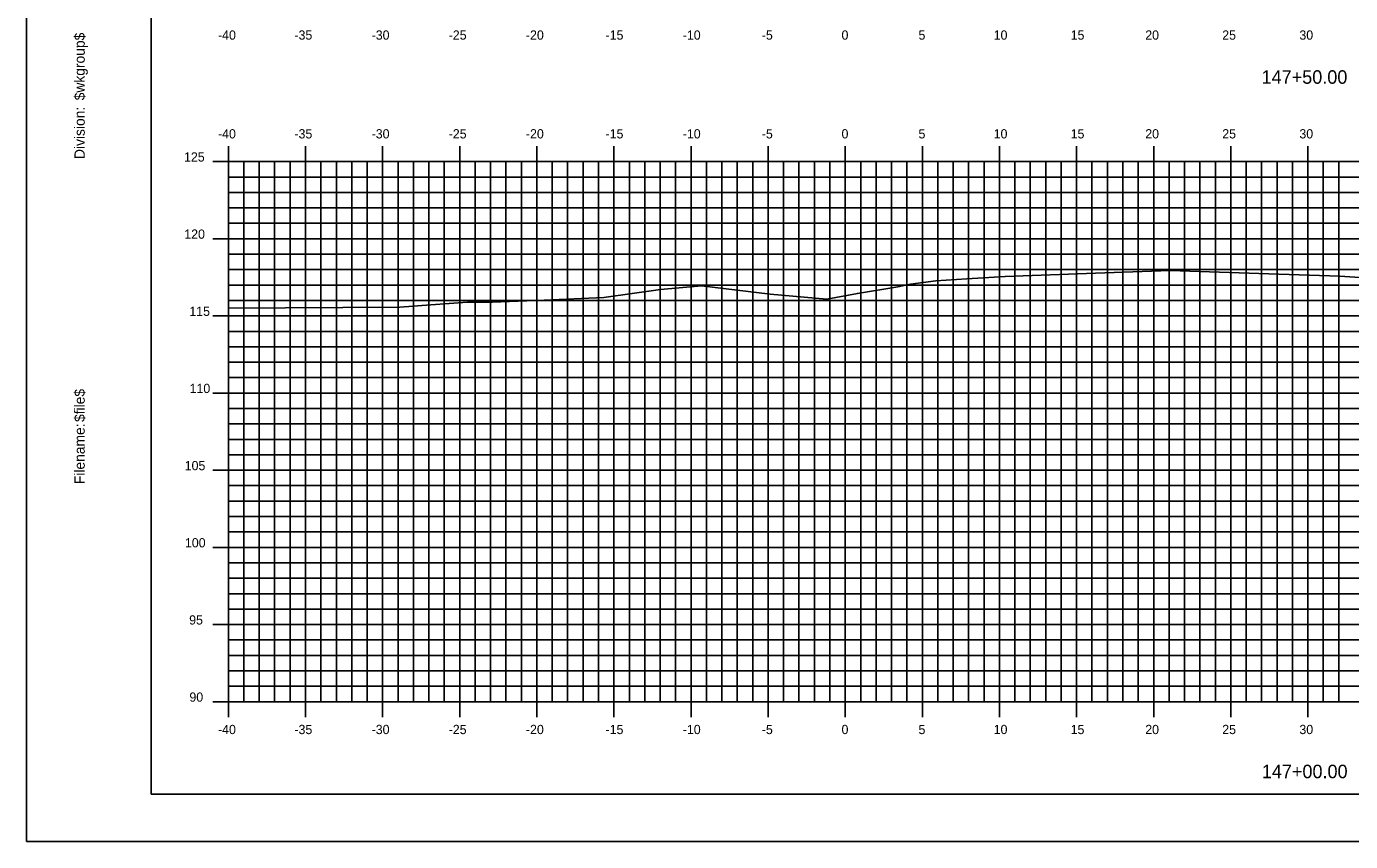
# Model space of a CAD drawing. Extents: x 850598 to 870284, y 366541 to 366651.
# Drawn here: x 850597.8 to 850683.7, y 366541.2 to 366594 of the extents above; entities that cross this region are included whole.
import ezdxf

# ---------------------------------------------------------------- set-up
doc = ezdxf.new("R2010")
doc.units = 0
for name, color, linetype in [('BORDER', 7, 'Continuous'), ('H_V ANNOTATION', 7, 'Continuous'), ('MAJOR', 7, 'Continuous'), ('MINOR', 7, 'Continuous'), ('PLOT BOUNDARY', 7, 'Continuous'), ('S_Roadway_Centerline', 7, 'Continuous')]:
    doc.layers.add(name, color=color, linetype=linetype)

msp = doc.modelspace()

# ---------------------------------------------------------------- linework, layer by layer
at = {"layer": 'BORDER'}
for p, q in [((850605.897, 366649.225), (850605.897, 366544.225)), ((850605.897, 366544.225), (850765.897, 366544.225))]:
    msp.add_line(p, q, dxfattribs=at)
at = {"layer": 'MAJOR'}
for p, q in [((850610.897, 366586.227), (850610.897, 366585.225)), ((850610.897, 366586.227), (850610.897, 366585.225)), ((850615.897, 366586.227), (850615.897, 366585.225)), ((850615.897, 366586.227), (850615.897, 366585.225)), ((850620.897, 366586.227), (850620.897, 366585.225)), ((850620.897, 366586.227), (850620.897, 366585.225)), ((850625.897, 366586.227), (850625.897, 366585.225)), ((850625.897, 366586.227), (850625.897, 366585.225)), ((850630.897, 366586.227), (850630.897, 366585.225)), ((850630.897, 366586.227), (850630.897, 366585.225)), ((850635.897, 366586.227), (850635.897, 366585.225)), ((850635.897, 366586.227), (850635.897, 366585.225)), ((850640.897, 366586.227), (850640.897, 366585.225)), ((850640.897, 366586.227), (850640.897, 366585.225)), ((850645.897, 366586.227), (850645.897, 366585.225)), ((850645.897, 366586.227), (850645.897, 366585.225)), ((850650.897, 366586.227), (850650.897, 366585.225)), ((850650.897, 366586.227), (850650.897, 366585.225)), ((850655.897, 366586.227), (850655.897, 366585.225)), ((850655.897, 366586.227), (850655.897, 366585.225)), ((850660.897, 366586.227), (850660.897, 366585.225)), ((850660.897, 366586.227), (850660.897, 366585.225)), ((850665.897, 366586.227), (850665.897, 366585.225)), ((850665.897, 366586.227), (850665.897, 366585.225)), ((850670.897, 366586.227), (850670.897, 366585.225)), ((850670.897, 366586.227), (850670.897, 366585.225)), ((850675.897, 366586.227), (850675.897, 366585.225)), ((850675.897, 366586.227), (850675.897, 366585.225)), ((850680.897, 366586.227), (850680.897, 366585.225)), ((850680.897, 366586.227), (850680.897, 366585.225)), ((850609.895, 366585.225), (850610.897, 366585.225)), ((850609.895, 366585.225), (850610.897, 366585.225)), ((850610.897, 366585.225), (850750.897, 366585.225)), ((850610.897, 366550.225), (850610.897, 366585.225)), ((850610.897, 366550.225), (850610.897, 366585.225)), ((850610.897, 366585.225), (850750.897, 366585.225)), ((850610.897, 366585.225), (850750.897, 366585.225)), ((850610.897, 366550.225), (850610.897, 366585.225)), ((850610.897, 366550.225), (850610.897, 366585.225)), ((850610.897, 366585.225), (850750.897, 366585.225)), ((850615.897, 366550.225), (850615.897, 366585.225)), ((850615.897, 366550.225), (850615.897, 366585.225)), ((850620.897, 366550.225), (850620.897, 366585.225)), ((850620.897, 366550.225), (850620.897, 366585.225)), ((850625.897, 366550.225), (850625.897, 366585.225)), ((850625.897, 366550.225), (850625.897, 366585.225)), ((850630.897, 366550.225), (850630.897, 366585.225)), ((850630.897, 366550.225), (850630.897, 366585.225)), ((850635.897, 366550.225), (850635.897, 366585.225)), ((850635.897, 366550.225), (850635.897, 366585.225)), ((850640.897, 366550.225), (850640.897, 366585.225)), ((850640.897, 366550.225), (850640.897, 366585.225)), ((850645.897, 366550.225), (850645.897, 366585.225)), ((850645.897, 366550.225), (850645.897, 366585.225)), ((850650.897, 366550.225), (850650.897, 366585.225)), ((850650.897, 366550.225), (850650.897, 366585.225)), ((850655.897, 366550.225), (850655.897, 366585.225)), ((850655.897, 366550.225), (850655.897, 366585.225)), ((850660.897, 366550.225), (850660.897, 366585.225)), ((850660.897, 366550.225), (850660.897, 366585.225)), ((850665.897, 366550.225), (850665.897, 366585.225)), ((850665.897, 366550.225), (850665.897, 366585.225)), ((850670.897, 366550.225), (850670.897, 366585.225)), ((850670.897, 366550.225), (850670.897, 366585.225)), ((850675.897, 366550.225), (850675.897, 366585.225)), ((850675.897, 366550.225), (850675.897, 366585.225)), ((850680.897, 366550.225), (850680.897, 366585.225)), ((850680.897, 366550.225), (850680.897, 366585.225)), ((850609.895, 366580.225), (850610.897, 366580.225)), ((850609.895, 366580.225), (850610.897, 366580.225)), ((850610.897, 366580.225), (850750.897, 366580.225)), ((850610.897, 366580.225), (850750.897, 366580.225)), ((850609.895, 366575.225), (850610.897, 366575.225)), ((850609.895, 366575.225), (850610.897, 366575.225)), ((850610.897, 366575.225), (850750.897, 366575.225)), ((850610.897, 366575.225), (850750.897, 366575.225)), ((850609.895, 366570.225), (850610.897, 366570.225)), ((850609.895, 366570.225), (850610.897, 366570.225)), ((850610.897, 366570.225), (850750.897, 366570.225)), ((850610.897, 366570.225), (850750.897, 366570.225)), ((850609.895, 366565.225), (850610.897, 366565.225)), ((850609.895, 366565.225), (850610.897, 366565.225)), ((850610.897, 366565.225), (850750.897, 366565.225)), ((850610.897, 366565.225), (850750.897, 366565.225)), ((850609.895, 366560.225), (850610.897, 366560.225)), ((850609.895, 366560.225), (850610.897, 366560.225)), ((850610.897, 366560.225), (850750.897, 366560.225)), ((850610.897, 366560.225), (850750.897, 366560.225)), ((850609.895, 366555.225), (850610.897, 366555.225)), ((850609.895, 366555.225), (850610.897, 366555.225)), ((850610.897, 366555.225), (850750.897, 366555.225)), ((850610.897, 366555.225), (850750.897, 366555.225)), ((850609.895, 366550.225), (850610.897, 366550.225)), ((850609.895, 366550.225), (850610.897, 366550.225)), ((850610.897, 366550.225), (850750.897, 366550.225)), ((850610.897, 366550.225), (850750.897, 366550.225)), ((850610.897, 366549.223), (850610.897, 366550.225)), ((850610.897, 366550.225), (850750.897, 366550.225)), ((850610.897, 366550.225), (850750.897, 366550.225)), ((850610.897, 366549.223), (850610.897, 366550.225)), ((850615.897, 366549.223), (850615.897, 366550.225)), ((850615.897, 366549.223), (850615.897, 366550.225)), ((850620.897, 366549.223), (850620.897, 366550.225)), ((850620.897, 366549.223), (850620.897, 366550.225)), ((850625.897, 366549.223), (850625.897, 366550.225)), ((850625.897, 366549.223), (850625.897, 366550.225)), ((850630.897, 366549.223), (850630.897, 366550.225)), ((850630.897, 366549.223), (850630.897, 366550.225)), ((850635.897, 366549.223), (850635.897, 366550.225)), ((850635.897, 366549.223), (850635.897, 366550.225)), ((850640.897, 366549.223), (850640.897, 366550.225)), ((850640.897, 366549.223), (850640.897, 366550.225)), ((850645.897, 366549.223), (850645.897, 366550.225)), ((850645.897, 366549.223), (850645.897, 366550.225)), ((850650.897, 366549.223), (850650.897, 366550.225)), ((850650.897, 366549.223), (850650.897, 366550.225)), ((850655.897, 366549.223), (850655.897, 366550.225)), ((850655.897, 366549.223), (850655.897, 366550.225)), ((850660.897, 366549.223), (850660.897, 366550.225)), ((850660.897, 366549.223), (850660.897, 366550.225)), ((850665.897, 366549.223), (850665.897, 366550.225)), ((850665.897, 366549.223), (850665.897, 366550.225)), ((850670.897, 366549.223), (850670.897, 366550.225)), ((850670.897, 366549.223), (850670.897, 366550.225)), ((850675.897, 366549.223), (850675.897, 366550.225)), ((850675.897, 366549.223), (850675.897, 366550.225)), ((850680.897, 366549.223), (850680.897, 366550.225)), ((850680.897, 366549.223), (850680.897, 366550.225))]:
    msp.add_line(p, q, dxfattribs=at)
at = {"layer": 'MINOR'}
for p, q in [((850611.897, 366550.225), (850611.897, 366585.225)), ((850611.897, 366550.225), (850611.897, 366585.225)), ((850612.897, 366550.225), (850612.897, 366585.225)), ((850612.897, 366550.225), (850612.897, 366585.225)), ((850613.897, 366550.225), (850613.897, 366585.225)), ((850613.897, 366550.225), (850613.897, 366585.225)), ((850614.897, 366550.225), (850614.897, 366585.225)), ((850614.897, 366550.225), (850614.897, 366585.225)), ((850616.897, 366550.225), (850616.897, 366585.225)), ((850616.897, 366550.225), (850616.897, 366585.225)), ((850617.897, 366550.225), (850617.897, 366585.225)), ((850617.897, 366550.225), (850617.897, 366585.225)), ((850618.897, 366550.225), (850618.897, 366585.225)), ((850618.897, 366550.225), (850618.897, 366585.225)), ((850619.897, 366550.225), (850619.897, 366585.225)), ((850619.897, 366550.225), (850619.897, 366585.225)), ((850621.897, 366550.225), (850621.897, 366585.225)), ((850621.897, 366550.225), (850621.897, 366585.225)), ((850622.897, 366550.225), (850622.897, 366585.225)), ((850622.897, 366550.225), (850622.897, 366585.225)), ((850623.897, 366550.225), (850623.897, 366585.225)), ((850623.897, 366550.225), (850623.897, 366585.225)), ((850624.897, 366550.225), (850624.897, 366585.225)), ((850624.897, 366550.225), (850624.897, 366585.225)), ((850626.897, 366550.225), (850626.897, 366585.225)), ((850626.897, 366550.225), (850626.897, 366585.225)), ((850627.897, 366550.225), (850627.897, 366585.225)), ((850627.897, 366550.225), (850627.897, 366585.225)), ((850628.897, 366550.225), (850628.897, 366585.225)), ((850628.897, 366550.225), (850628.897, 366585.225)), ((850629.897, 366550.225), (850629.897, 366585.225)), ((850629.897, 366550.225), (850629.897, 366585.225)), ((850631.897, 366550.225), (850631.897, 366585.225)), ((850631.897, 366550.225), (850631.897, 366585.225)), ((850632.897, 366550.225), (850632.897, 366585.225)), ((850632.897, 366550.225), (850632.897, 366585.225)), ((850633.897, 366550.225), (850633.897, 366585.225)), ((850633.897, 366550.225), (850633.897, 366585.225)), ((850634.897, 366550.225), (850634.897, 366585.225)), ((850634.897, 366550.225), (850634.897, 366585.225)), ((850636.897, 366550.225), (850636.897, 366585.225)), ((850636.897, 366550.225), (850636.897, 366585.225)), ((850637.897, 366550.225), (850637.897, 366585.225)), ((850637.897, 366550.225), (850637.897, 366585.225)), ((850638.897, 366550.225), (850638.897, 366585.225)), ((850638.897, 366550.225), (850638.897, 366585.225)), ((850639.897, 366550.225), (850639.897, 366585.225)), ((850639.897, 366550.225), (850639.897, 366585.225)), ((850641.897, 366550.225), (850641.897, 366585.225)), ((850641.897, 366550.225), (850641.897, 366585.225)), ((850642.897, 366550.225), (850642.897, 366585.225)), ((850642.897, 366550.225), (850642.897, 366585.225)), ((850643.897, 366550.225), (850643.897, 366585.225)), ((850643.897, 366550.225), (850643.897, 366585.225)), ((850644.897, 366550.225), (850644.897, 366585.225)), ((850644.897, 366550.225), (850644.897, 366585.225)), ((850646.897, 366550.225), (850646.897, 366585.225)), ((850646.897, 366550.225), (850646.897, 366585.225)), ((850647.897, 366550.225), (850647.897, 366585.225)), ((850647.897, 366550.225), (850647.897, 366585.225)), ((850648.897, 366550.225), (850648.897, 366585.225)), ((850648.897, 366550.225), (850648.897, 366585.225)), ((850649.897, 366550.225), (850649.897, 366585.225)), ((850649.897, 366550.225), (850649.897, 366585.225)), ((850651.897, 366550.225), (850651.897, 366585.225)), ((850651.897, 366550.225), (850651.897, 366585.225)), ((850652.897, 366550.225), (850652.897, 366585.225)), ((850652.897, 366550.225), (850652.897, 366585.225)), ((850653.897, 366550.225), (850653.897, 366585.225)), ((850653.897, 366550.225), (850653.897, 366585.225)), ((850654.897, 366550.225), (850654.897, 366585.225)), ((850654.897, 366550.225), (850654.897, 366585.225)), ((850656.897, 366550.225), (850656.897, 366585.225)), ((850656.897, 366550.225), (850656.897, 366585.225)), ((850657.897, 366550.225), (850657.897, 366585.225)), ((850657.897, 366550.225), (850657.897, 366585.225)), ((850658.897, 366550.225), (850658.897, 366585.225)), ((850658.897, 366550.225), (850658.897, 366585.225)), ((850659.897, 366550.225), (850659.897, 366585.225)), ((850659.897, 366550.225), (850659.897, 366585.225)), ((850661.897, 366550.225), (850661.897, 366585.225)), ((850661.897, 366550.225), (850661.897, 366585.225)), ((850662.897, 366550.225), (850662.897, 366585.225)), ((850662.897, 366550.225), (850662.897, 366585.225)), ((850663.897, 366550.225), (850663.897, 366585.225)), ((850663.897, 366550.225), (850663.897, 366585.225)), ((850664.897, 366550.225), (850664.897, 366585.225)), ((850664.897, 366550.225), (850664.897, 366585.225)), ((850666.897, 366550.225), (850666.897, 366585.225)), ((850666.897, 366550.225), (850666.897, 366585.225)), ((850667.897, 366550.225), (850667.897, 366585.225)), ((850667.897, 366550.225), (850667.897, 366585.225)), ((850668.897, 366550.225), (850668.897, 366585.225)), ((850668.897, 366550.225), (850668.897, 366585.225)), ((850669.897, 366550.225), (850669.897, 366585.225)), ((850669.897, 366550.225), (850669.897, 366585.225)), ((850671.897, 366550.225), (850671.897, 366585.225)), ((850671.897, 366550.225), (850671.897, 366585.225)), ((850672.897, 366550.225), (850672.897, 366585.225)), ((850672.897, 366550.225), (850672.897, 366585.225)), ((850673.897, 366550.225), (850673.897, 366585.225)), ((850673.897, 366550.225), (850673.897, 366585.225)), ((850674.897, 366550.225), (850674.897, 366585.225)), ((850674.897, 366550.225), (850674.897, 366585.225)), ((850676.897, 366550.225), (850676.897, 366585.225)), ((850676.897, 366550.225), (850676.897, 366585.225)), ((850677.897, 366550.225), (850677.897, 366585.225)), ((850677.897, 366550.225), (850677.897, 366585.225)), ((850678.897, 366550.225), (850678.897, 366585.225)), ((850678.897, 366550.225), (850678.897, 366585.225)), ((850679.897, 366550.225), (850679.897, 366585.225)), ((850679.897, 366550.225), (850679.897, 366585.225)), ((850681.897, 366550.225), (850681.897, 366585.225)), ((850681.897, 366550.225), (850681.897, 366585.225)), ((850682.897, 366550.225), (850682.897, 366585.225)), ((850682.897, 366550.225), (850682.897, 366585.225)), ((850610.897, 366584.225), (850750.897, 366584.225)), ((850610.897, 366584.225), (850611.899, 366584.225)), ((850610.897, 366584.225), (850750.897, 366584.225)), ((850610.897, 366584.225), (850611.899, 366584.225)), ((850610.897, 366583.225), (850750.897, 366583.225)), ((850610.897, 366583.225), (850611.899, 366583.225)), ((850610.897, 366583.225), (850750.897, 366583.225)), ((850610.897, 366583.225), (850611.899, 366583.225)), ((850610.897, 366582.225), (850750.897, 366582.225)), ((850610.897, 366582.225), (850611.899, 366582.225)), ((850610.897, 366582.225), (850750.897, 366582.225)), ((850610.897, 366582.225), (850611.899, 366582.225)), ((850610.897, 366581.225), (850750.897, 366581.225)), ((850610.897, 366581.225), (850611.899, 366581.225)), ((850610.897, 366581.225), (850750.897, 366581.225)), ((850610.897, 366581.225), (850611.899, 366581.225)), ((850610.897, 366579.225), (850750.897, 366579.225)), ((850610.897, 366579.225), (850611.899, 366579.225)), ((850610.897, 366579.225), (850750.897, 366579.225)), ((850610.897, 366579.225), (850611.899, 366579.225)), ((850610.897, 366578.225), (850750.897, 366578.225)), ((850610.897, 366578.225), (850611.899, 366578.225)), ((850610.897, 366578.225), (850750.897, 366578.225)), ((850610.897, 366578.225), (850611.899, 366578.225)), ((850610.897, 366577.225), (850750.897, 366577.225)), ((850610.897, 366577.225), (850611.899, 366577.225)), ((850610.897, 366577.225), (850750.897, 366577.225)), ((850610.897, 366577.225), (850611.899, 366577.225)), ((850610.897, 366576.225), (850750.897, 366576.225)), ((850610.897, 366576.225), (850611.899, 366576.225)), ((850610.897, 366576.225), (850750.897, 366576.225)), ((850610.897, 366576.225), (850611.899, 366576.225)), ((850610.897, 366574.225), (850750.897, 366574.225)), ((850610.897, 366574.225), (850611.899, 366574.225)), ((850610.897, 366574.225), (850750.897, 366574.225)), ((850610.897, 366574.225), (850611.899, 366574.225)), ((850610.897, 366573.225), (850750.897, 366573.225)), ((850610.897, 366573.225), (850611.899, 366573.225)), ((850610.897, 366573.225), (850750.897, 366573.225)), ((850610.897, 366573.225), (850611.899, 366573.225)), ((850610.897, 366572.225), (850750.897, 366572.225)), ((850610.897, 366572.225), (850611.899, 366572.225)), ((850610.897, 366572.225), (850750.897, 366572.225)), ((850610.897, 366572.225), (850611.899, 366572.225)), ((850610.897, 366571.225), (850750.897, 366571.225)), ((850610.897, 366571.225), (850611.899, 366571.225)), ((850610.897, 366571.225), (850750.897, 366571.225)), ((850610.897, 366571.225), (850611.899, 366571.225)), ((850610.897, 366569.225), (850750.897, 366569.225)), ((850610.897, 366569.225), (850611.899, 366569.225)), ((850610.897, 366569.225), (850750.897, 366569.225)), ((850610.897, 366569.225), (850611.899, 366569.225)), ((850610.897, 366568.225), (850750.897, 366568.225)), ((850610.897, 366568.225), (850611.899, 366568.225)), ((850610.897, 366568.225), (850750.897, 366568.225)), ((850610.897, 366568.225), (850611.899, 366568.225)), ((850610.897, 366567.225), (850750.897, 366567.225)), ((850610.897, 366567.225), (850611.899, 366567.225)), ((850610.897, 366567.225), (850750.897, 366567.225)), ((850610.897, 366567.225), (850611.899, 366567.225)), ((850610.897, 366566.225), (850750.897, 366566.225)), ((850610.897, 366566.225), (850611.899, 366566.225)), ((850610.897, 366566.225), (850750.897, 366566.225)), ((850610.897, 366566.225), (850611.899, 366566.225)), ((850610.897, 366564.225), (850750.897, 366564.225)), ((850610.897, 366564.225), (850611.899, 366564.225)), ((850610.897, 366564.225), (850750.897, 366564.225)), ((850610.897, 366564.225), (850611.899, 366564.225)), ((850610.897, 366563.225), (850750.897, 366563.225)), ((850610.897, 366563.225), (850611.899, 366563.225)), ((850610.897, 366563.225), (850750.897, 366563.225)), ((850610.897, 366563.225), (850611.899, 366563.225)), ((850610.897, 366562.225), (850750.897, 366562.225)), ((850610.897, 366562.225), (850611.899, 366562.225)), ((850610.897, 366562.225), (850750.897, 366562.225)), ((850610.897, 366562.225), (850611.899, 366562.225)), ((850610.897, 366561.225), (850750.897, 366561.225)), ((850610.897, 366561.225), (850611.899, 366561.225)), ((850610.897, 366561.225), (850750.897, 366561.225)), ((850610.897, 366561.225), (850611.899, 366561.225)), ((850610.897, 366559.225), (850750.897, 366559.225)), ((850610.897, 366559.225), (850611.899, 366559.225)), ((850610.897, 366559.225), (850750.897, 366559.225)), ((850610.897, 366559.225), (850611.899, 366559.225)), ((850610.897, 366558.225), (850750.897, 366558.225)), ((850610.897, 366558.225), (850611.899, 366558.225)), ((850610.897, 366558.225), (850750.897, 366558.225)), ((850610.897, 366558.225), (850611.899, 366558.225)), ((850610.897, 366557.225), (850750.897, 366557.225)), ((850610.897, 366557.225), (850611.899, 366557.225)), ((850610.897, 366557.225), (850750.897, 366557.225)), ((850610.897, 366557.225), (850611.899, 366557.225)), ((850610.897, 366556.225), (850750.897, 366556.225)), ((850610.897, 366556.225), (850611.899, 366556.225)), ((850610.897, 366556.225), (850750.897, 366556.225)), ((850610.897, 366556.225), (850611.899, 366556.225)), ((850610.897, 366554.225), (850750.897, 366554.225)), ((850610.897, 366554.225), (850611.899, 366554.225)), ((850610.897, 366554.225), (850750.897, 366554.225)), ((850610.897, 366554.225), (850611.899, 366554.225)), ((850610.897, 366553.225), (850750.897, 366553.225)), ((850610.897, 366553.225), (850611.899, 366553.225)), ((850610.897, 366553.225), (850750.897, 366553.225)), ((850610.897, 366553.225), (850611.899, 366553.225)), ((850610.897, 366552.225), (850750.897, 366552.225)), ((850610.897, 366552.225), (850611.899, 366552.225)), ((850610.897, 366552.225), (850750.897, 366552.225)), ((850610.897, 366552.225), (850611.899, 366552.225)), ((850610.897, 366551.225), (850750.897, 366551.225)), ((850610.897, 366551.225), (850611.899, 366551.225)), ((850610.897, 366551.225), (850750.897, 366551.225)), ((850610.897, 366551.225), (850611.899, 366551.225))]:
    msp.add_line(p, q, dxfattribs=at)
at = {"layer": 'PLOT BOUNDARY'}
msp.add_lwpolyline([(850597.804, 366541.166), (850767.804, 366541.166), (850767.804, 366651.166), (850597.804, 366651.166)], close=True, dxfattribs=at)
at = {"layer": 'S_Roadway_Centerline'}
msp.add_lwpolyline([(850610.897, 366575.731), (850622.017, 366575.785), (850624.024, 366575.934), (850626.412, 366576.113), (850628.003, 366576.122), (850631.38, 366576.248), (850635.233, 366576.426), (850638.926, 366576.943), (850641.582, 366577.181), (850646.018, 366576.626), (850649.712, 366576.319), (850651.69, 366576.683), (850654.298, 366577.1), (850655.138, 366577.284), (850656.774, 366577.5), (850658.772, 366577.621), (850661.276, 366577.781), (850667.124, 366577.993), (850671.96, 366578.162), (850678.36, 366577.949), (850682.961, 366577.809), (850685.235, 366577.644)], dxfattribs=at)

# ---------------------------------------------------------------- texts
at = {"layer": 'BORDER'}
for s, p in [('$wkgroup$', (850601.582, 366589.195)), ('Division:', (850601.582, 366585.391)), ('$file$', (850601.582, 366568.351)), ('Filename:', (850601.582, 366564.324))]:
    msp.add_text(s, height=0.6696, rotation=90, dxfattribs=at).set_placement(p)
at = {"layer": 'H_V ANNOTATION'}
for s, height, p in [('-40', 0.6, (850610.223, 366593.125)), ('-35', 0.6, (850615.177, 366593.125)), ('-30', 0.6, (850620.185, 366593.125)), ('-25', 0.6, (850625.182, 366593.125)), ('-20', 0.6, (850630.19, 366593.125)), ('-15', 0.6, (850635.354, 366593.125)), ('-10', 0.6, (850640.362, 366593.125)), ('-5', 0.6, (850645.487, 366593.125)), ('0', 0.6, (850650.656, 366593.125)), ('5', 0.6, (850655.648, 366593.125)), ('10', 0.6, (850660.522, 366593.125)), ('15', 0.6, (850665.514, 366593.125)), ('20', 0.6, (850670.351, 366593.125)), ('25', 0.6, (850675.343, 366593.125)), ('30', 0.6, (850680.346, 366593.125)), ('147+50.00', 0.875, (850677.893, 366590.268)), ('-40', 0.6, (850610.223, 366586.725)), ('-35', 0.6, (850615.177, 366586.725)), ('-30', 0.6, (850620.185, 366586.725)), ('-25', 0.6, (850625.182, 366586.725)), ('-20', 0.6, (850630.19, 366586.725)), ('-15', 0.6, (850635.354, 366586.725)), ('-10', 0.6, (850640.362, 366586.725)), ('-5', 0.6, (850645.487, 366586.725)), ('0', 0.6, (850650.656, 366586.725)), ('5', 0.6, (850655.648, 366586.725)), ('10', 0.6, (850660.522, 366586.725)), ('15', 0.6, (850665.514, 366586.725)), ('20', 0.6, (850670.351, 366586.725)), ('25', 0.6, (850675.343, 366586.725)), ('30', 0.6, (850680.346, 366586.725)), ('125', 0.6, (850608.021, 366585.225)), ('120', 0.6, (850608.037, 366580.225)), ('115', 0.6, (850608.364, 366575.225)), ('110', 0.6, (850608.38, 366570.225)), ('105', 0.6, (850608.064, 366565.225)), ('100', 0.6, (850608.08, 366560.225)), ('95', 0.6, (850608.353, 366555.225)), ('90', 0.6, (850608.369, 366550.225)), ('-40', 0.6, (850610.223, 366548.125)), ('-35', 0.6, (850615.177, 366548.125)), ('-30', 0.6, (850620.185, 366548.125)), ('-25', 0.6, (850625.182, 366548.125)), ('-20', 0.6, (850630.19, 366548.125)), ('-15', 0.6, (850635.354, 366548.125)), ('-10', 0.6, (850640.362, 366548.125)), ('-5', 0.6, (850645.487, 366548.125)), ('0', 0.6, (850650.656, 366548.125)), ('5', 0.6, (850655.648, 366548.125)), ('10', 0.6, (850660.522, 366548.125)), ('15', 0.6, (850665.514, 366548.125)), ('20', 0.6, (850670.351, 366548.125)), ('25', 0.6, (850675.343, 366548.125)), ('30', 0.6, (850680.346, 366548.125)), ('147+00.00', 0.875, (850677.908, 366545.268))]:
    msp.add_text(s, height=height, dxfattribs=at).set_placement(p)

doc.saveas('drawing.dxf')
